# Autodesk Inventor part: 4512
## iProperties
Author: Administrator
Shininess: 50.0
PropertySet Name: _Private Model Information
Created: 2001-08
Part Number: 4512
Document SubType Name: Modeling
Designer: Administrator
Material: Aluminum-6061
Description: 8020 Corner Bracket, Series 10-15
Control State: 0
Master: False
Checked Out: False
PropertySet Name: Design Tracking Control
Density: 2.71
Volumn: 13.82357110679213
Area: 57.930010493818166
PropertySet Name: Model Information
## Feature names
1. Block [Extrusion]
2. FrontHoles [Extrusion]
3. FillHolesR [Extrusion]
4. FillHolesL [Extrusion]
5. TopHoles [Extrusion]
6. Shape [Extrusion]
7. WidthCut [Extrusion]
8. SlotCuts [Extrusion]
9. CutSides [Extrusion]
